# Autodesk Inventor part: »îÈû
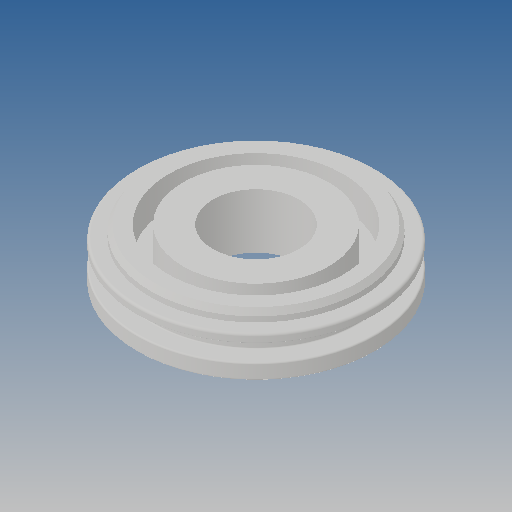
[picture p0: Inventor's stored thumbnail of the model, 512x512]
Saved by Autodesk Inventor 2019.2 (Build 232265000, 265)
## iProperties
Created: 2013-07
Part Number: »îÈû
Material: Ogólny
Document SubType Name: Modeling
Designer: CADENGINEERING4
Density: 1 g/cm^3
Appearance: Domyślna
Author: CADENGINEERING4
Revision Number: ÈÎºÎ
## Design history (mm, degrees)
feature "ÇÐ³ý-À­Éì1"
node "Bryła1"
